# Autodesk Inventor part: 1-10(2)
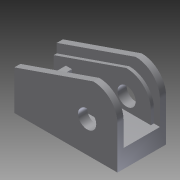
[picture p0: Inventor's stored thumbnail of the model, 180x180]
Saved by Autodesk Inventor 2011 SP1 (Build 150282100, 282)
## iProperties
Created: 2014-02
Part Number: 1-10(2)
Document SubType Name: Modeling
Designer: Administrator
Density: 1 g/cm^3
Author: Administrator
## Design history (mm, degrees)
sketch "草图1"
  geometry: L1 (-15, 8)-(15, 8); L2 (15, 8)-(15, -8); L3 (15, -8)-(-15, -8); L4 (-15, -8)-(-15, 8); 3 further points
  constraints: 8 end point, 2 midpoint, 2 parallel, 1 horizontal, 1 horizontal alignment, 1 perpendicular, 1 vertical alignment
extrude "拉伸1" new body sketch "草图1" distance "d0" = 6; taper "d1" = 0 deg
sketch "草图2"
  geometry: L1 (30, 6)-(0, 6) reference; L2 (0, 0)-(0, 6) reference; L3 (30, 0)-(0, 0) reference; L4 (30, 0)-(30, 6) reference; L5 (30, 0)-(30, 14); L6 (30, 0)-(-4, 0); L7 (-4, 0)-(-4, 13); L8 (-4, 13)-(22, 22); A1 r 8 centre (22, 14) between (30, 14) and (22, 22); 1 further point
  constraints: 8 end point, 2 point on circle, 2 point on line, 1 centre point
  dimensions: "d2" = 14 distance of L3.start L5.end; "d3" = 34 distance of L3.start L6.end; "d6" = 13 distance of L6.end L7.end
extrude "拉伸2" join sketch "草图2" distance "d7" = 2; taper "d8" = 0 deg
sketch "草图3"
  geometry: L1 (0, 0)-(0, -6) reference; L2 (-4, 0)-(0, 0) reference; L3 (-4, -13)-(-4, 0) reference; L4 (22, -22)-(-4, -13) reference; L5 (0, -6)-(30, -6) reference; L6 (-4, 0)-(-4, -10); L7 (30, -6)-(30, -14) reference; L8 (27.998, -6)-(27.998, -10.368); L9 (19.906, -18.275)-(-4, -10); A1 r 8 centre (19.998, -10.276) between (19.906, -18.275) and (27.998, -10.368); 1 further point
  constraints: 6 end point, 2 parallel, 2 point on circle, 2 point on line, 1 centre point
extrude "拉伸3" join sketch "草图3" distance "d9" = 1; taper "d10" = 0 deg
mirror "镜像1"
sketch "草图4"
  geometry: L1 (-15, -5)-(12.998, -5) reference; L2 (-15, 5)-(-13, 5); L3 (-13, 5)-(-13, -5); L4 (-13, -5)-(-15, -5); L5 (-15, -5)-(-15, 5); 1 further point
  constraints: 8 end point, 2 parallel, 1 horizontal, 1 perpendicular, 1 point on line
extrude "拉伸4" join sketch "草图4" distance "d11" = 3; taper "d12" = 0 deg
sketch "草图5"
  geometry: L1 (-12.998, 5)-(13, 5) reference; L2 (13, -5)-(-12.998, -5) reference; L3 (5, -2)-(-5, -2); L4 (5, 2)-(-5, 2); A1 r 2 centre (5, 0) between (5, -2) and (5, 2); A2 r 2 centre (-5, 0) between (-5, 2) and (-5, -2); 1 further point
  constraints: 4 end point, 4 point on circle, 2 centre point, 2 tangent
  dimensions: "d13" = 4 diameter of A1; "d14" = 4 diameter of A2
extrude "拉伸5" cut sketch "草图5" stored distance "d15" = 3; taper "d16" = 0 deg
sketch "草图6"
  geometry: C1 r 3 at (23.998, 10.276); A1 r 8 centre (23.998, 10.276) between (31.998, 10.368) and (23.906, 18.275) reference; 1 further point
  constraints: 1 centre point, 1 coincident
  dimensions: "d17" = 6 diameter of C1
extrude "拉伸6" cut sketch "草图6" stored distance "d18" = 3; taper "d19" = 0 deg
node "实体1"
